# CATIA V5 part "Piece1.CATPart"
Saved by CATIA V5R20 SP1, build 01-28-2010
Part number: Piece1
Bounding box of the stored display mesh (mm): x 96.953 to 142.462, y 28.535 to 298.765, z -447.978 to -273.061
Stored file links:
  C:\Users\RENARD Simon\Documents\Cours IFMA\2ème année\IAO\Piece1.CATPart
  C:\Users\RENARD Simon\Documents\Cours IFMA\2ème année\IAO\Trainattero.CATProduct
  C:\Users\RENARD Simon\Documents\Cours IFMA\2ème année\IAO\Sqpiece1.CATPart
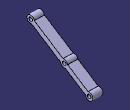
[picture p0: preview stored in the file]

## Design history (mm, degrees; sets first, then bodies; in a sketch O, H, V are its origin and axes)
External parameters (linked from other documents)
  External.Longueur1 = 280 mm
Set1
  Plane1: linked copy from another document
  Line1 to Line3: linked copy from another document
Body1 (main body)
  Sketch1 on Plane1, origin (116.3072, -2.382, 0), H (-0.0205, -0.9998, 0), V (0, 0, 1)
    arc A1 centre (-285.8299, -433.052) radius 15 from (-281.4474, -418.7065) to (-271.0863, -435.8135) ccw
    point P1 (-285.8299, -433.052)
    arc A2 centre (-183.1883, -370.8854) radius 15 from (-178.8057, -356.5399) to (-197.9319, -368.124) ccw
    point P2 (-183.1883, -370.8854)
    arc A3 centre (-46.3327, -287.9966) radius 15 from (-31.3327, -287.9966) to (-61.0763, -285.2351) ccw
    point P3 (-46.3327, -287.9966)
    reference projected point E1 (-46.3327, -287.9966) from Line1
    reference projected point E2 (-183.1883, -370.8854) from Line2
    reference projected point E3 (-285.8299, -433.052) from Line3
    line L1 (-61.0763, -285.2351) -> (-178.8057, -356.5399)
    point P6 (-50.7152, -302.3421)
    line L2 (-50.7152, -302.3421) -> (-168.4446, -373.6468)
    point P8 (-197.9319, -368.124)
    line L3 (-197.9319, -368.124) -> (-281.4474, -418.7065)
    point P10 (-187.5708, -385.2309)
    line L4 (-187.5708, -385.2309) -> (-271.0863, -435.8135)
    reference projected point E4 (-285.8299, -433.052) from Line3
    reference projected point E5 (-183.1883, -370.8854) from Line2
    arc A4 centre (-46.3327, -287.9966) radius 15 from (-50.7152, -302.3421) to (-31.3327, -287.9966) ccw
    point P12 (-31.3327, -287.9966)
    point P13 (-31.3327, -287.9966)
    arc A5 centre (-183.1883, -370.8854) radius 15 from (-187.5708, -385.2309) to (-168.4446, -373.6468) ccw
    radius A3 = 15
    radius A2 = 15
    radius A1 = 15
    distance E4 L4 = 10
    distance L3 L4 = 20
    distance E5 L4 = 10
    coincidence: P3 E1, P2 E2, P1 E3, P8 L1, P10 L2, P10 A2, P6 A3, A3 A4, A2 A5, P12 P13
    parallelism: L2 L1
  Pad1: profile Sketch1, direction (0.9998, -0.0205, 0), length 20, mirrored extent
  Sketch2 on end face of Pad1, origin (136.303, -2.7915, 0), H (0.0205, 0.9998, 0), V (0, 0, 1)
    circle A1 centre (183.1883, -370.8854) radius 7.5
    point P1 (183.1883, -370.8854)
    circle A2 centre (285.8299, -433.052) radius 7.5
    point P2 (285.8299, -433.052)
    circle A3 centre (46.3327, -287.9966) radius 7.5
    point P3 (46.3327, -287.9966)
    reference projected point E1 (46.3327, -287.9966) from Line1
    reference projected point E2 (183.1883, -370.8854) from Line2
    reference projected point E3 (285.8299, -433.052) from Line3
    radius A3 = 7.5
    radius A1 = 7.5
    radius A2 = 7.5
    coincidence: P3 E1, P1 E2, P2 E3
  Pocket1: profile Sketch2, direction (-0.9998, 0.0205, 0), length 40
